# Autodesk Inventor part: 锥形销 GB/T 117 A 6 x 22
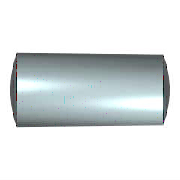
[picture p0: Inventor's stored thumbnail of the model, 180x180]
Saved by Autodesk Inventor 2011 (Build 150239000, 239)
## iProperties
Created: 2010-02
Part Number: 锥形销 GB/T 117 A 6 x 22
Material: 低炭钢
Description: 锥形销
Document SubType Name: Modeling
Standard: GB/T 117-2000
Designer: Administrator
Standard Revision: 2000
Standards Organization: GB
Language: zh-CN
Size Designation: A 6 x 22
Categories: <MemberInstance><Categories><Category DisplayName="紧固件" InternalName="e4da775c-781d-43d5-af7c-5136215cf5a6" Mnemonic="FSTN"><Category DisplayName="销" InternalNa
Density: 1 g/cm^3
IsCustomPart: 1
Author: Administrator
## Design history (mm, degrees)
sketch "Sketch1"
  geometry: L1 (0, 0)-(22, 0); L2 (0.8, 3)-(21.2, 3.204); A1 r 6.025 centre (6.025, 0) between (0.8, 3) and (0, 0); A2 r 6.816 centre (15.184, 0) between (22, 0) and (21.2, 3.204); 1 further point
  constraints: 4 end point, 4 point on circle, 2 centre point, 2 point on line, 1 coincident, 1 horizontal
  dimensions: "d0" = 22 distance of L1.end L1.start (= NLG); "d1" = 0.8 horizontal distance of L1.start L2.start (= KAH); "d2" = 0.8 horizontal distance of L1.end L2.end (= KAH); "d3" = 6 diameter of L2.start L1 (= NND); "d5" = 6.408 diameter of L2.end L1 (computed from NND, NLG1, PIT)
revolve "Body" sketch "Sketch1" stored, may be unused: angle "d4" = 90 deg
body "Solid1"
other parameters: "NND" = 6 [user parameter; used in 2 equation terms], "NLG" = 22 [user parameter; used in 1 equation term], "KAH" = 0.8 [user parameter; used in 4 equation terms], "NLG1" = 20.4 [user parameter; used in 1 equation term], "d24" = 0, "d35" = 0.8 (= KAH), "d36" = 0.8 (= KAH)
